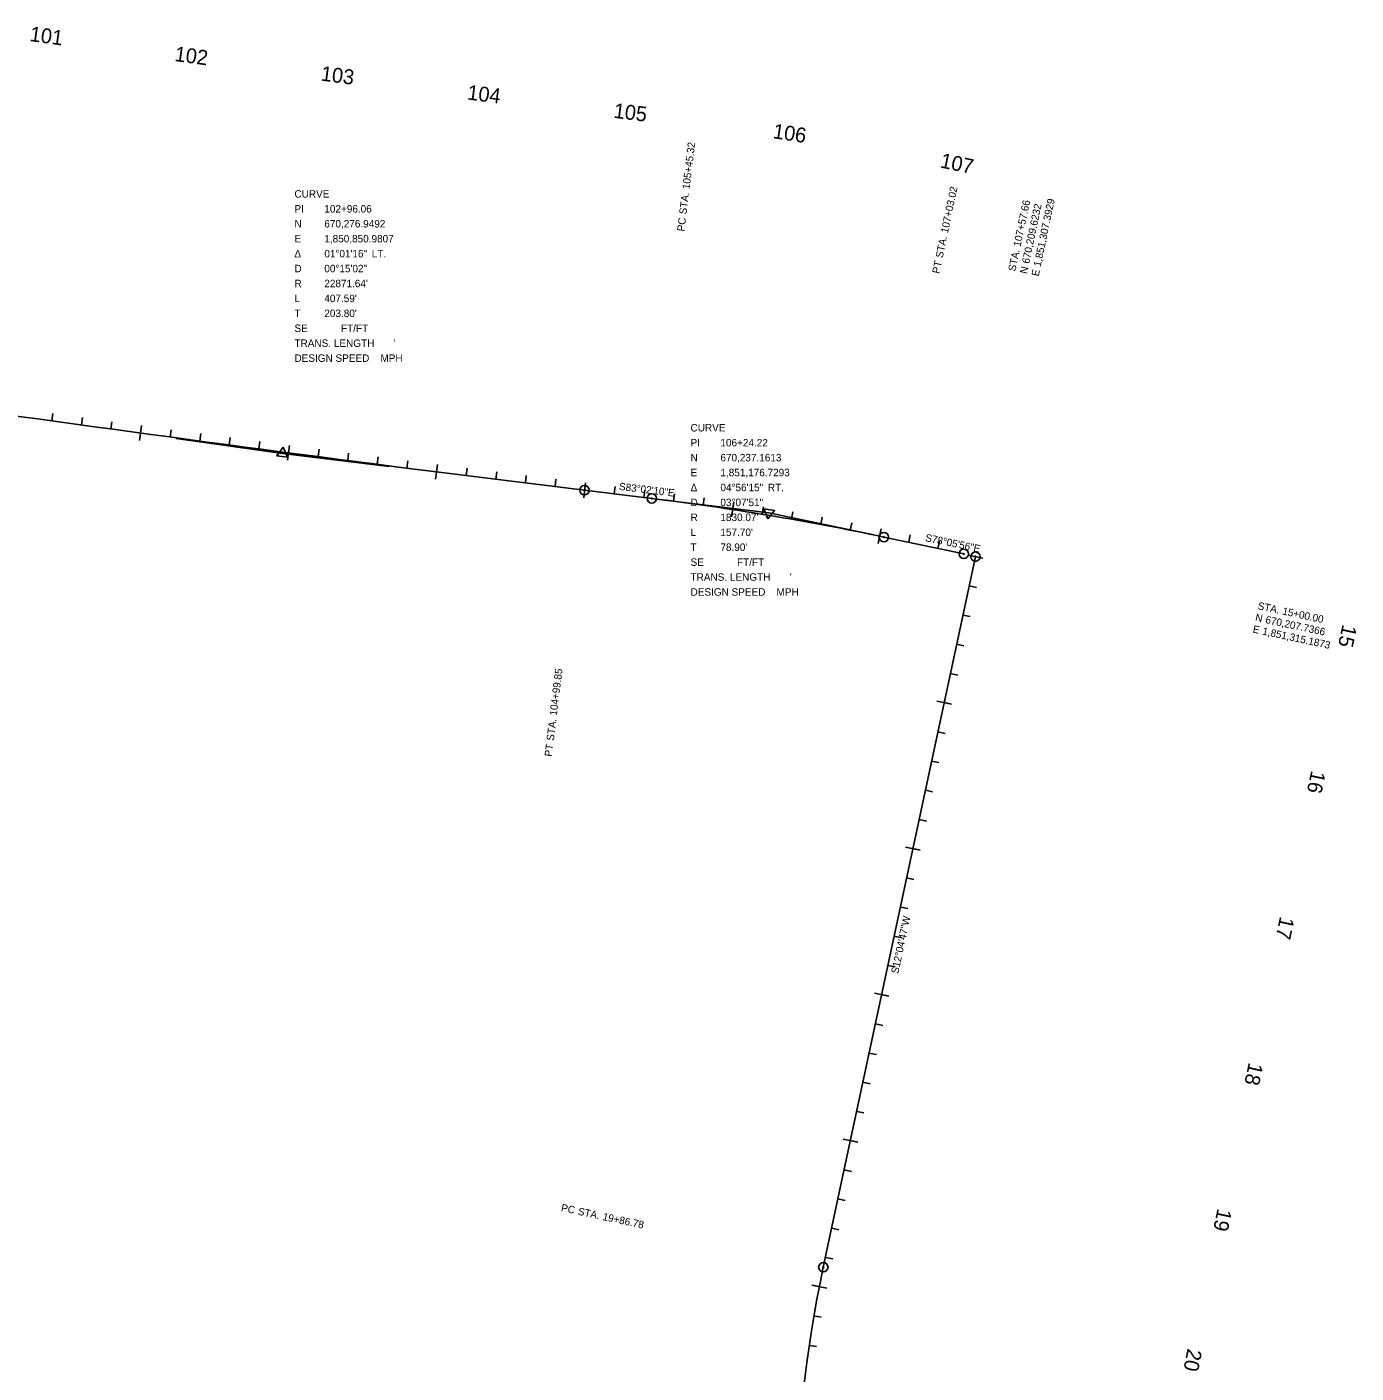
# Model space of a CAD drawing. Extents: x 1849564 to 1851966, y 666816 to 670715.
# Drawn here: x 1850680 to 1851570, y 669661 to 670563 of the extents above; entities that cross this region are included whole.
import ezdxf

# ---------------------------------------------------------------- set-up
doc = ezdxf.new("R2010")
doc.units = 0
for name, color, linetype in [('CONCEPT - PAVEMENT MARKING - Crosswalk Long', 7, 'Continuous'), ('CONCEPT - PAVEMENT MARKING - Crosswalk Parallel', 7, 'Continuous'), ('CONCEPT - PAVEMENT MARKING - Stop Bar', 7, 'Continuous'), ('CONCEPT - PAVEMENT MARKING - Striping - Yellow', 7, 'Continuous'), ('Default', 7, 'Continuous'), ('DES - DRG - Special Ditches', 7, 'Continuous'), ('DES - MODEL - Lines - Barrier', 7, 'Continuous')]:
    doc.layers.add(name, color=color, linetype=linetype)

msp = doc.modelspace()

# ---------------------------------------------------------------- linework, layer by layer
at = {"layer": 'CONCEPT - PAVEMENT MARKING - Crosswalk Parallel'}
for p, q in [((1850850.98, 670276.95), (1850779.68, 670286.95)), ((1850850.98, 670276.95), (1850850.98, 670276.95)), ((1850850.98, 670276.95), (1850922.45, 670268.22)), ((1851176.73, 670237.16), (1851105.26, 670245.89)), ((1851176.73, 670237.16), (1851176.73, 670237.16)), ((1851176.73, 670237.16), (1851247.18, 670222.31))]:
    msp.add_line(p, q, dxfattribs=at)
for points in [[(1850851.52, 670281.07), (1850847.14, 670275.36), (1850854.28, 670274.42)], [(1851176.05, 670233.06), (1851180.62, 670238.62), (1851173.52, 670239.8)]]:
    msp.add_lwpolyline(points, close=True, dxfattribs=at)
at = {"layer": 'CONCEPT - PAVEMENT MARKING - Stop Bar'}
for p, q in [((1850696.44, 670298.68), (1850697.12, 670303.61)), ((1850716.25, 670295.95), (1850716.93, 670300.88)), ((1850736.07, 670293.24), (1850736.74, 670298.17)), ((1850756.56, 670295.5), (1850755.21, 670285.59)), ((1850775.71, 670287.87), (1850776.37, 670292.8)), ((1850795.53, 670285.21), (1850796.19, 670290.15)), ((1850815.35, 670282.57), (1850816.01, 670287.5)), ((1850835.18, 670279.94), (1850835.83, 670284.88)), ((1850855.66, 670282.29), (1850854.36, 670272.38)), ((1850874.84, 670274.75), (1850875.48, 670279.69)), ((1850894.68, 670272.17), (1850895.31, 670277.11)), ((1850914.51, 670269.62), (1850915.15, 670274.56)), ((1850934.35, 670267.08), (1850934.98, 670272.02)), ((1850954.82, 670269.52), (1850953.56, 670259.6)), ((1850974.03, 670262.06), (1850974.65, 670267)), ((1850993.88, 670259.57), (1850994.49, 670264.52)), ((1851013.73, 670257.11), (1851014.34, 670262.05)), ((1851033.57, 670254.66), (1851034.18, 670259.6)), ((1851054.03, 670257.18), (1851052.82, 670247.26)), ((1851073.28, 670249.8), (1851073.88, 670254.74)), ((1851093.13, 670247.37), (1851093.73, 670252.32)), ((1851112.98, 670244.89), (1851113.62, 670249.83)), ((1851132.79, 670242.2), (1851133.49, 670247.13)), ((1851153.34, 670244.23), (1851151.83, 670234.34)), ((1851172.34, 670236.16), (1851173.14, 670241.08)), ((1851192.05, 670232.82), (1851192.91, 670237.73)), ((1851211.74, 670229.27), (1851212.65, 670234.16)), ((1851231.38, 670225.5), (1851232.34, 670230.38)), ((1851252, 670226.4), (1851249.95, 670216.62)), ((1851270.55, 670217.39), (1851271.57, 670222.26)), ((1851290.12, 670213.26), (1851291.14, 670218.14)), ((1851320.08, 670206.69), (1851310.3, 670208.78)), ((1851311, 670188.18), (1851315.87, 670187.14)), ((1851306.82, 670168.62), (1851311.69, 670167.58)), ((1851302.63, 670149.07), (1851307.5, 670148.02)), ((1851298.45, 670129.51), (1851303.32, 670128.47)), ((1851299.15, 670108.9), (1851289.37, 670111)), ((1851290.07, 670090.39), (1851294.94, 670089.35)), ((1851285.89, 670070.84), (1851290.76, 670069.79)), ((1851281.7, 670051.28), (1851286.57, 670050.24)), ((1851277.52, 670031.72), (1851282.39, 670030.68)), ((1851278.22, 670011.12), (1851268.44, 670013.21)), ((1851269.15, 669992.61), (1851274.02, 669991.57)), ((1851264.96, 669973.05), (1851269.83, 669972.01)), ((1851260.78, 669953.49), (1851265.65, 669952.45)), ((1851256.59, 669933.94), (1851261.46, 669932.89)), ((1851257.29, 669913.33), (1851247.52, 669915.43)), ((1851248.22, 669894.82), (1851253.09, 669893.78)), ((1851244.03, 669875.27), (1851248.9, 669874.22)), ((1851239.85, 669855.71), (1851244.72, 669854.67)), ((1851235.66, 669836.15), (1851240.53, 669835.11)), ((1851236.37, 669815.55), (1851226.59, 669817.64)), ((1851227.29, 669797.04), (1851232.16, 669795.99)), ((1851223.11, 669777.48), (1851227.98, 669776.44)), ((1851218.92, 669757.92), (1851223.79, 669756.88)), ((1851214.74, 669738.36), (1851219.61, 669737.32)), ((1851215.56, 669717.82), (1851205.75, 669719.75)), ((1851207.03, 669699.12), (1851211.93, 669698.27)), ((1851203.88, 669679.37), (1851208.81, 669678.64))]:
    msp.add_line(p, q, dxfattribs=at)
at = {"layer": 'CONCEPT - PAVEMENT MARKING - Striping - Yellow'}
for p, q in [((1850755.89, 670290.54), (1850756.55, 670295.48)), ((1850855.01, 670277.34), (1850855.66, 670282.27)), ((1850954.19, 670264.56), (1850954.82, 670269.5)), ((1851054.03, 670257.18), (1851052.82, 670247.24)), ((1851152.58, 670239.29), (1851153.33, 670244.21)), ((1851250.98, 670221.51), (1851251.99, 670226.39)), ((1851320.08, 670206.69), (1851310.28, 670208.79)), ((1851294.26, 670109.95), (1851299.13, 670108.91)), ((1851273.33, 670012.17), (1851278.2, 670011.12)), ((1851252.41, 669914.38), (1851257.28, 669913.34)), ((1851231.48, 669816.59), (1851236.35, 669815.55)), ((1851215.56, 669717.82), (1851205.73, 669719.76))]:
    msp.add_line(p, q, dxfattribs=at)
for centre, radius in [((1851053.28, 670252.24), 3.14), ((1851053.28, 670252.24), 0.33), ((1851098.41, 670246.73), 3.14), ((1851098.41, 670246.73), 0.33), ((1851253.93, 670220.89), 3.14), ((1851253.93, 670220.89), 0.33), ((1851307.39, 670209.62), 3.14), ((1851307.39, 670209.62), 0.33), ((1851315.19, 670207.74), 3.14), ((1851315.19, 670207.74), 0.33), ((1851213.32, 669731.73), 3.14), ((1851213.32, 669731.73), 0.33)]:
    msp.add_circle(centre, radius, dxfattribs=at)
at = {"layer": 'Default'}
for p, q in [((1851053.28, 670252.24), (1851098.41, 670246.73)), ((1851253.93, 670220.89), (1851307.39, 670209.62)), ((1851315.19, 670207.74), (1851213.32, 669731.73))]:
    msp.add_line(p, q, dxfattribs=at)
for centre, radius, start, end in [((1853826.28, 692955.15), 22871.64, 262.015164, 263.036208), ((1850876.53, 668430.16), 1830.07, 78.09878, 83.03621), ((1852013.7, 669560.44), 818.51, 167.92032, 215.80713)]:
    msp.add_arc(centre, radius, start, end, dxfattribs=at)
at = {"layer": 'DES - DRG - Special Ditches'}
for p, q in [((1851053.28, 670252.24), (1851098.41, 670246.73)), ((1851253.93, 670220.89), (1851307.39, 670209.62)), ((1851315.19, 670207.74), (1851213.32, 669731.73))]:
    msp.add_line(p, q, dxfattribs=at)
for centre, radius, start, end in [((1853826.28, 692955.15), 22871.64, 262.015164, 263.036208), ((1850876.53, 668430.16), 1830.07, 78.09878, 83.03621), ((1852013.7, 669560.44), 818.51, 167.92032, 215.80713)]:
    msp.add_arc(centre, radius, start, end, dxfattribs=at)
at = {"layer": 'DES - MODEL - Lines - Barrier'}
msp.add_circle((1851315.19, 670207.74), 0.05, dxfattribs=at)

# ---------------------------------------------------------------- texts
at = {"layer": 'CONCEPT - PAVEMENT MARKING - Crosswalk Long'}
for s, rotation, p in [('105+45.32', 83.03621, (1851123.69, 670453.67)), ('107+03.02', 78.09878, (1851296.77, 670424.13)), (' STA. ', 83.03621, (1851121.41, 670435)), ('PC', 83.03621, (1851120.23, 670425.4)), (' STA. ', 78.09878, (1851292.89, 670405.72)), ('PT', 78.09878, (1851291.06, 670397.02)), ('104+99.85', 83.03621, (1851034.81, 670101.07)), (' STA. ', 83.03621, (1851032.53, 670082.4)), ('PT', 83.03621, (1851031.45, 670073.57)), ('PC', 347.92032, (1851037.3, 669769.4)), (' STA. ', 347.92032, (1851046.76, 669767.38)), ('19+86.78', 347.92032, (1851065.16, 669763.44))]:
    msp.add_text(s, height=4.98, rotation=rotation, dxfattribs=at).set_placement(p)
for s, p in [('CURVE    ', (1850859.02, 670448.24)), ('PI', (1850859.02, 670438.24)), ('102+96.06', (1850879.02, 670438.24)), ('N', (1850859.02, 670428.24)), ('670,276.9492', (1850879.02, 670428.24)), ('E', (1850859.02, 670418.24)), ('1,850,850.9807', (1850879.02, 670418.24)), ('Δ', (1850859.02, 670408.24)), ('01°01\'16"', (1850879.02, 670408.24)), (' LT.', (1850908.93, 670408.24)), ('D', (1850859.02, 670398.24)), ('00°15\'02"', (1850879.02, 670398.24)), ('R', (1850859.02, 670388.24)), ("22871.64'", (1850879.02, 670388.24)), ('L', (1850859.02, 670378.24)), ("407.59'", (1850879.02, 670378.24)), ('T', (1850859.02, 670368.24)), ("203.80'", (1850879.02, 670368.24)), ('SE', (1850859.02, 670358.24)), ('      FT/FT', (1850879.02, 670358.24)), ("TRANS. LENGTH       '", (1850859.02, 670348.24)), ('DESIGN SPEED    MPH', (1850859.02, 670338.24)), ('CURVE    ', (1851124.37, 670291.6)), ('PI', (1851124.37, 670281.6)), ('106+24.22', (1851144.37, 670281.6)), ('N', (1851124.37, 670271.6)), ('670,237.1613', (1851144.37, 670271.6)), ('E', (1851124.37, 670261.6)), ('1,851,176.7293', (1851144.37, 670261.6)), ('Δ', (1851124.37, 670251.6)), ('04°56\'15"', (1851144.37, 670251.6)), (' RT.', (1851174.28, 670251.6)), ('D', (1851124.37, 670241.6)), ('03°07\'51"', (1851144.37, 670241.6)), ('R', (1851124.37, 670231.6)), ("1830.07'", (1851144.37, 670231.6)), ('L', (1851124.37, 670221.6)), ("157.70'", (1851144.37, 670221.6)), ('T', (1851124.37, 670211.6)), ("78.90'", (1851144.37, 670211.6)), ('SE', (1851124.37, 670201.6)), ('      FT/FT', (1851144.37, 670201.6)), ("TRANS. LENGTH       '", (1851124.37, 670191.6)), ('DESIGN SPEED    MPH', (1851124.37, 670181.6))]:
    msp.add_text(s, height=5, dxfattribs=at).set_placement(p)
at = {"layer": 'CONCEPT - PAVEMENT MARKING - Crosswalk Parallel'}
for s, rotation, p in [('107+57.66', 78.09878, (1851345.44, 670415.08)), ('670,209.6232', 78.09878, (1851351.19, 670403.72)), ('1,851,307.3929', 78.09878, (1851358.91, 670401.7)), ('STA. ', 78.09878, (1851341.96, 670398.56)), ('N ', 78.09878, (1851349.76, 670396.91)), ('E ', 78.09878, (1851357.56, 670395.27)), ('S83°02\'10"E', 353.03621, (1851076.21, 670252.46)), ('S78°05\'56"E', 348.09878, (1851281.28, 670218.19)), ('STA. ', 347.92032, (1851504.01, 670172.58)), ('15+00.00', 347.92032, (1851520.52, 670169.05)), ('N ', 347.92032, (1851502.34, 670164.79)), ('670,207.7366', 347.92032, (1851509.15, 670163.33)), ('E ', 347.92032, (1851500.68, 670157)), ('1,851,315.1873', 347.92032, (1851507.1, 670155.62)), ('S12°04\'47"W', 77.92032, (1851263.49, 669928.05))]:
    msp.add_text(s, height=4.98, rotation=rotation, dxfattribs=at).set_placement(p)
at = {"layer": 'CONCEPT - PAVEMENT MARKING - Stop Bar'}
for s, rotation, p in [('101', 352.03455, (1850681.24, 670553.2)), ('102', 352.28506, (1850778.31, 670539.79)), ('103', 352.53557, (1850876.29, 670526.68)), ('104', 352.78608, (1850974.41, 670514)), ('105', 353.03621, (1851072.49, 670501.75)), ('106', 351.32423, (1851179.13, 670488.13)), ('107', 348.19344, (1851291.08, 670468.53)), ('15', 257.92032, (1851561.21, 670162.71)), ('16', 257.92032, (1851540.28, 670064.89)), ('17', 257.92032, (1851519.35, 669967.1)), ('18', 257.92032, (1851498.42, 669869.33)), ('19', 257.92032, (1851477.5, 669771.54)), ('20', 258.84543, (1851457.37, 669677.68))]:
    msp.add_text(s, height=9.96, rotation=rotation, dxfattribs=at).set_placement(p)
at = {"layer": 'CONCEPT - PAVEMENT MARKING - Striping - Yellow'}
for s, rotation, p in [('105', 353.03621, (1851072.49, 670501.75)), ('15', 257.92032, (1851561.21, 670162.71)), ('20', 258.84543, (1851457.37, 669677.68))]:
    msp.add_text(s, height=9.96, rotation=rotation, dxfattribs=at).set_placement(p)

doc.saveas('drawing.dxf')
